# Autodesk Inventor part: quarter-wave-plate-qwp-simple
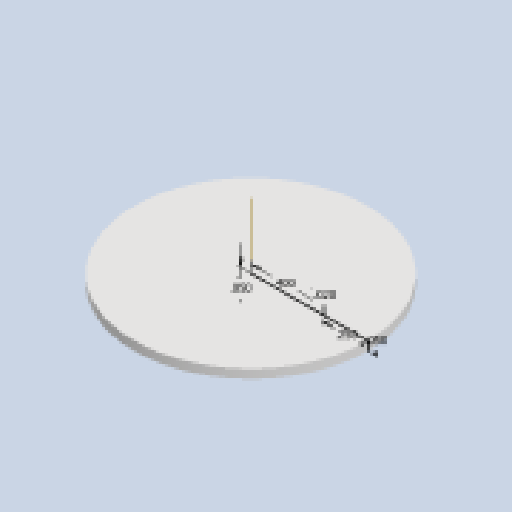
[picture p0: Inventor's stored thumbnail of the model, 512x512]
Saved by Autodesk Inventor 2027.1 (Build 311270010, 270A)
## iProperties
Created: 2026-07
Part Number: quarter-wave-plate-qwp-simple
Material: Generic
Document SubType Name: Modeling
Designer: dunge
Density: 1 g/cm^3
Appearance: Default
Author: dunge
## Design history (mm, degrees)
sketch "Sketch1"
  geometry: L1 (0, 0.635)-(10.16, 0.635); L2 (10.16, 0.635)-(10.16, -0.635); L3 (10.16, -0.635)-(0, -0.635); L4 (0, -0.635)-(0, 0.635); L5 (0, 0.635)-(10.16, -0.635); L6 (10.16, 0.635)-(0, -0.635); L7 (10.16, 0.635)-(10.668, 0.635); L8 (10.668, 0.635)-(16.51, 0.635); L9 (16.51, 0.635)-(16.51, -0.635); L10 (16.51, -0.635)-(10.668, -0.635); L11 (10.668, -0.635)-(10.16, -0.635); 3 further points
  constraints: 22 end point, 3 midpoint, 3 parallel, 3 perpendicular, 2 horizontal, 1 coincident, 1 vertical alignment
  dimensions: "d0" = 1.27 distance of L3.end L1.start; "d1" = 10.16 distance of L1.start L1.end; "d2" = 1.27 distance of L8.end L9.end; "d3" = 0.508 distance of L1.end L7.end; "d4" = 6.35 distance between parallel lines of L9 L2
revolve "Revolution1" stored, may be unused: angle "d5" = 360 deg
workpoint "Work Point1"
  workaxis "Work Axis1"
body "Solid1"
